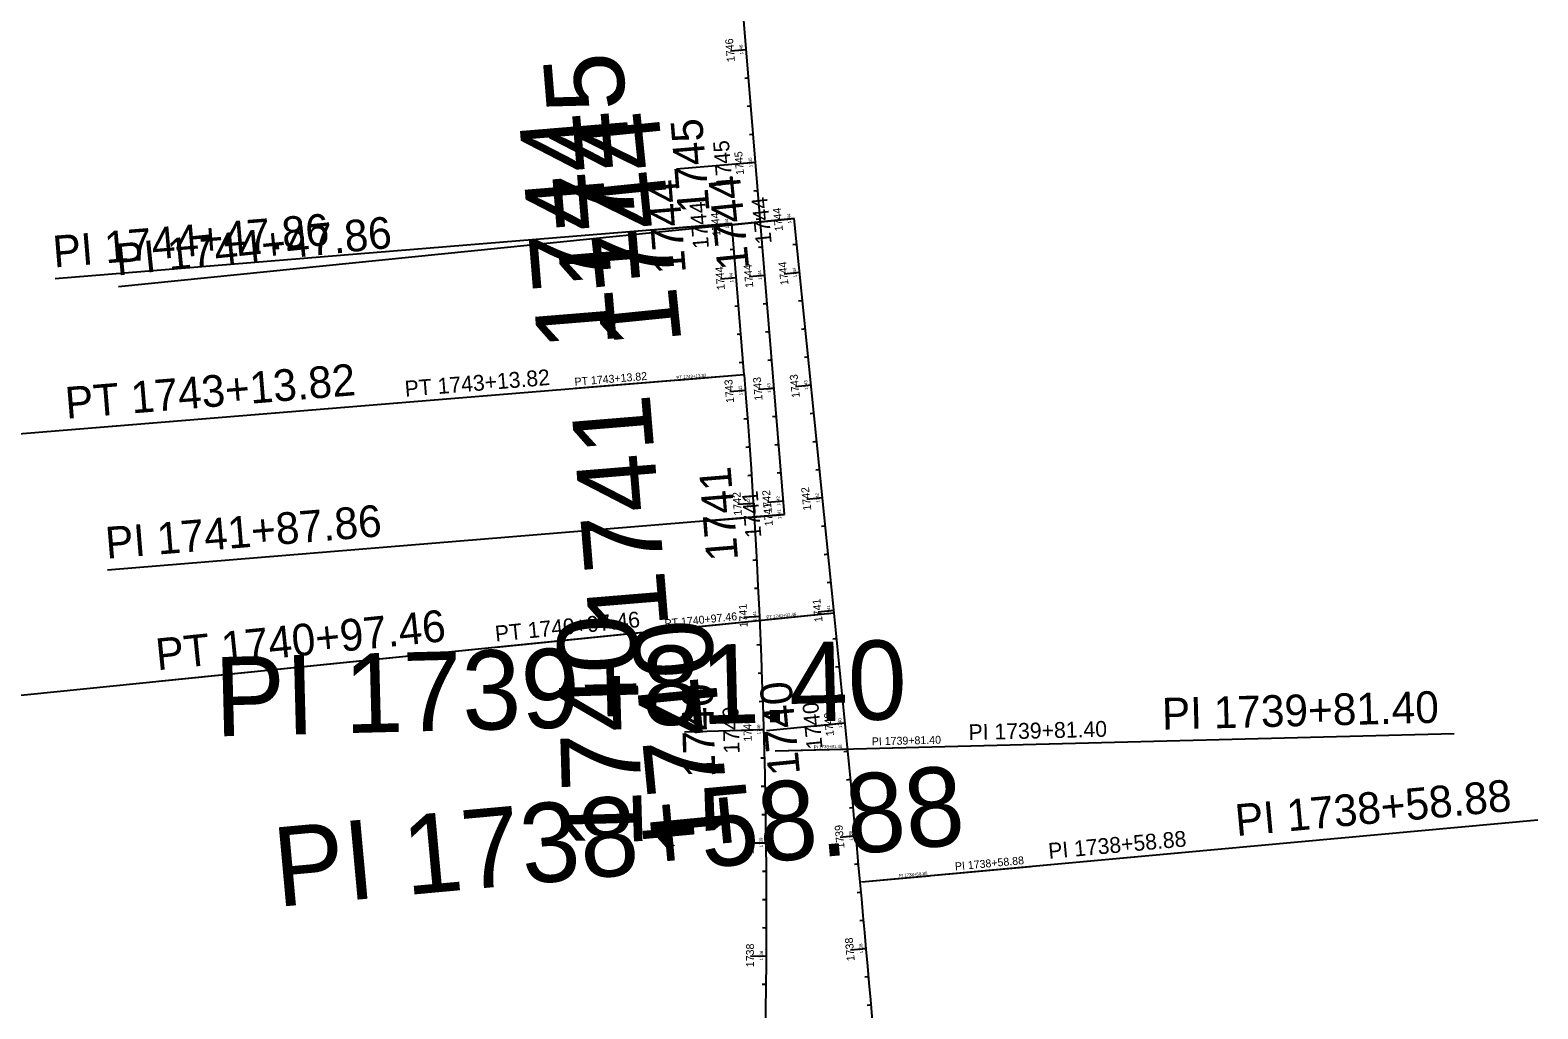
# Model space of a CAD drawing. Extents: x 353835 to 363333, y 126218 to 205387.
# Drawn here: x 360814 to 362146, y 132953 to 133817 of the extents above; entities that cross this region are included whole.
import ezdxf

# ---------------------------------------------------------------- set-up
doc = ezdxf.new("R2010")
doc.units = 0
for name, color, linetype in [('P_ALI_100_PIData', 7, 'Continuous'), ('P_ALI_100_Sta', 7, 'Continuous'), ('P_ALI_100_Tic', 7, 'Continuous'), ('P_ALI_20', 7, 'Continuous'), ('P_ALI_200_PIData', 7, 'Continuous'), ('P_ALI_200_Sta', 7, 'Continuous'), ('P_ALI_200_Tic', 7, 'Continuous'), ('P_ALI_20_PIData', 7, 'Continuous'), ('P_ALI_20_Sta', 7, 'Continuous'), ('P_ALI_20_Tic', 7, 'Continuous'), ('P_ALI_500_PIData', 7, 'Continuous'), ('P_ALI_500_Sta', 7, 'Continuous'), ('P_ALI_50_PIData', 7, 'Continuous'), ('P_ALI_50_Sta', 7, 'Continuous'), ('P_ALI_50_Tic', 7, 'Continuous')]:
    doc.layers.add(name, color=color, linetype=linetype)

msp = doc.modelspace()

# ---------------------------------------------------------------- linework, layer by layer
for points in [[(361494.2, 133603.3), (361494.2, 133603.3)], [(361504.3, 133503.8), (361504.3, 133503.8)], [(361514.3, 133404.3), (361514.4, 133404.3)], [(361524.4, 133304.9), (361524.4, 133304.9)], [(361543.8, 133105.8), (361543.8, 133105.8)], [(361552.9, 133006.2), (361552.9, 133006.2)]]:
    msp.add_lwpolyline(points)
at = {"layer": 'P_ALI_100_PIData'}
for points in [[(361445.2, 133512.8), (361146.2, 133488.4)], [(361445.2, 133512.8), (361385.4, 133507.9)], [(361524.7, 133302.3), (361226.2, 133272.1)], [(361524.7, 133302.3), (361465, 133296.3)], [(361472.4, 133180.8), (361772.3, 133188.4)], [(361472.4, 133180.8), (361532.4, 133182.3)], [(361548.7, 133064.9), (361847.5, 133092.3)], [(361548.7, 133064.9), (361608.5, 133070.4)]]:
    msp.add_lwpolyline(points, dxfattribs=at)
at = {"layer": 'P_ALI_100_Tic'}
for points in [[(361440, 133799.5), (361447, 133800.1)], [(361385.4, 133694.7), (361455.2, 133700.5)], [(361441.2, 133699.3), (361455.2, 133700.5)], [(361364.6, 133640.7), (361434.3, 133646.4)], [(361419.7, 133643.9), (361489.4, 133650.9)], [(361420.4, 133645.3), (361434.3, 133646.4)], [(361475.5, 133649.5), (361489.4, 133650.9)], [(361431.2, 133598.2), (361438.2, 133598.7)], [(361456.4, 133600.2), (361463.4, 133600.8)], [(361487.2, 133602.6), (361494.2, 133603.3)], [(361439.4, 133498.5), (361446.4, 133499.1)], [(361464.6, 133500.5), (361471.5, 133501.1)], [(361497.3, 133503.1), (361504.3, 133503.8)], [(361507.4, 133403.6), (361514.4, 133404.3)], [(361446.4, 133398.9), (361453.4, 133399.3)], [(361472.7, 133400.9), (361479.7, 133401.5)], [(361410.9, 133383.6), (361480.7, 133389.4)], [(361410.9, 133383.6), (361480.7, 133389.4)], [(361466.7, 133388.2), (361480.7, 133389.4)], [(361466.7, 133388.2), (361480.7, 133389.4)], [(361451.8, 133299.1), (361458.8, 133299.5)], [(361517.5, 133304.1), (361524.4, 133304.9)], [(361464.7, 133198.6), (361534.3, 133205.3)], [(361520.4, 133204), (361534.3, 133205.3)], [(361392.5, 133197.5), (361462.5, 133199.5)], [(361448.5, 133199.1), (361462.5, 133199.5)], [(361457.5, 133099.5), (361464.5, 133099.5)], [(361536.8, 133105.1), (361543.8, 133105.8)], [(361545.9, 133005.6), (361552.9, 133006.2)], [(361457.8, 132999.6), (361464.8, 132999.5)]]:
    msp.add_lwpolyline(points, dxfattribs=at)
at = {"layer": 'P_ALI_20'}
for p, q in [((361480.7, 133389.4), (361189, 136946.6)), ((361445.2, 133512.8), (361434.3, 133646.4)), ((361524.7, 133302.3), (361489.4, 133650.9))]:
    msp.add_line(p, q, dxfattribs=at)
for centre, radius, start, end in [((355564.9, 133031.9), 5900, 358.21215, 4.67542), ((336651.9, 130783.1), 25000, 4.68978, 5.78337)]:
    msp.add_arc(centre, radius, start, end, dxfattribs=at)
at = {"layer": 'P_ALI_200_PIData'}
for points in [[(361434.3, 133646.4), (360836.3, 133597.5)], [(361489.4, 133650.9), (360892.4, 133590.5)], [(361489.4, 133650.9), (360892.4, 133590.5)], [(361445.2, 133512.8), (360847.2, 133463.9)], [(361480.7, 133389.4), (360882.7, 133340.3)], [(361524.7, 133302.3), (360927.7, 133241.9)], [(361472.4, 133180.8), (362072.2, 133195.9)], [(361548.7, 133064.9), (362146.2, 133119.7)]]:
    msp.add_lwpolyline(points, dxfattribs=at)
at = {"layer": 'P_ALI_200_Tic'}
for points in [[(361433.1, 133799), (361447, 133800.1)], [(361427.3, 133698.2), (361455.2, 133700.5)], [(361406.4, 133644.1), (361434.3, 133646.4)], [(361461.5, 133648.1), (361489.4, 133650.9)], [(361461.5, 133648.1), (361489.4, 133650.9)], [(361424.3, 133597.6), (361438.2, 133598.7)], [(361449.4, 133599.6), (361463.4, 133600.8)], [(361480.3, 133601.9), (361494.2, 133603.3)], [(361432.4, 133498), (361446.4, 133499.1)], [(361457.6, 133500), (361471.5, 133501.1)], [(361490.4, 133502.4), (361504.3, 133503.8)], [(361500.4, 133402.9), (361514.4, 133404.3)], [(361439.5, 133398.4), (361453.4, 133399.3)], [(361465.8, 133400.3), (361479.7, 133401.5)], [(361452.8, 133387.1), (361480.7, 133389.4)], [(361452.8, 133387.1), (361480.7, 133389.4)], [(361444.8, 133298.8), (361458.8, 133299.5)], [(361510.5, 133303.4), (361524.4, 133304.9)], [(361506.5, 133202.6), (361534.3, 133205.3)], [(361434.5, 133198.7), (361462.5, 133199.5)], [(361450.5, 133099.4), (361464.5, 133099.5)], [(361529.9, 133104.5), (361543.8, 133105.8)], [(361539, 133005), (361552.9, 133006.2)], [(361450.8, 132999.6), (361464.8, 132999.5)]]:
    msp.add_lwpolyline(points, dxfattribs=at)
at = {"layer": 'P_ALI_20_Tic'}
for points in [[(361444.2, 133799.9), (361447, 133800.1)], [(361447.7, 133775.1), (361449.1, 133775.2)], [(361449.7, 133750.2), (361451.1, 133750.3)], [(361451.8, 133725.3), (361453.1, 133725.4)], [(361452.4, 133700.2), (361455.2, 133700.5)], [(361455.8, 133675.4), (361457.2, 133675.5)], [(361431.5, 133646.2), (361434.3, 133646.4)], [(361457.9, 133650.5), (361459.3, 133650.6)], [(361486.6, 133650.7), (361489.4, 133650.9)], [(361434.8, 133623.5), (361436.2, 133623.6)], [(361459.9, 133625.6), (361461.3, 133625.7)], [(361490.3, 133628.1), (361491.7, 133628.2)], [(361435.4, 133598.5), (361438.2, 133598.7)], [(361460.6, 133600.6), (361463.4, 133600.8)], [(361491.4, 133603), (361494.2, 133603.3)], [(361495.3, 133578.3), (361496.7, 133578.5)], [(361438.9, 133573.7), (361440.3, 133573.8)], [(361464, 133575.8), (361465.4, 133575.9)], [(361466.1, 133550.8), (361467.5, 133551)], [(361497.8, 133553.4), (361499.2, 133553.6)], [(361440.9, 133548.8), (361442.3, 133548.9)], [(361442.9, 133523.9), (361444.3, 133524)], [(361468.1, 133525.9), (361469.5, 133526)], [(361500.4, 133528.6), (361501.8, 133528.7)], [(361443.6, 133498.8), (361446.4, 133499.1)], [(361468.7, 133500.9), (361471.5, 133501.1)], [(361501.5, 133503.6), (361504.3, 133503.8)], [(361446.9, 133474), (361448.3, 133474.1)], [(361472.2, 133476.1), (361473.6, 133476.2)], [(361505.4, 133478.8), (361506.8, 133479)], [(361448.7, 133449.1), (361450.1, 133449.2)], [(361474.2, 133451.2), (361475.6, 133451.3)], [(361507.9, 133453.9), (361509.3, 133454.1)], [(361450.4, 133424.2), (361451.8, 133424.3)], [(361476.3, 133426.3), (361477.7, 133426.4)], [(361510.4, 133429.1), (361511.8, 133429.2)], [(361511.6, 133404.1), (361514.4, 133404.3)], [(361450.6, 133399.1), (361453.4, 133399.3)], [(361476.9, 133401.2), (361479.7, 133401.5)], [(361477.9, 133389.1), (361480.7, 133389.4)], [(361477.9, 133389.1), (361480.7, 133389.4)], [(361515.5, 133379.3), (361516.9, 133379.5)], [(361453.5, 133374.3), (361454.9, 133374.4)], [(361518, 133354.5), (361519.4, 133354.6)], [(361454.9, 133349.3), (361456.3, 133349.4)], [(361456.2, 133324.4), (361457.6, 133324.4)], [(361520.5, 133329.6), (361521.9, 133329.7)], [(361456, 133299.3), (361458.8, 133299.5)], [(361521.6, 133304.6), (361524.4, 133304.9)], [(361458.5, 133274.4), (361459.9, 133274.5)], [(361525.5, 133279.8), (361526.9, 133280)], [(361459.5, 133249.4), (361460.9, 133249.5)], [(361528, 133255), (361529.4, 133255.1)], [(361460.3, 133224.5), (361461.7, 133224.5)], [(361530.5, 133230.1), (361531.9, 133230.2)], [(361531.5, 133205.1), (361534.3, 133205.3)], [(361459.7, 133199.4), (361462.5, 133199.5)], [(361535.3, 133180.3), (361536.7, 133180.5)], [(361461.8, 133174.5), (361463.2, 133174.5)], [(361537.7, 133155.4), (361539.1, 133155.6)], [(361462.3, 133149.5), (361463.7, 133149.5)], [(361462.8, 133124.5), (361464.1, 133124.5)], [(361540.1, 133130.6), (361541.5, 133130.7)], [(361461.7, 133099.5), (361464.5, 133099.5)], [(361541, 133105.5), (361543.8, 133105.8)], [(361463.3, 133074.5), (361464.7, 133074.5)], [(361544.7, 133080.8), (361546.1, 133080.9)], [(361463.5, 133049.5), (361464.9, 133049.5)], [(361547, 133055.9), (361548.4, 133056)], [(361549.3, 133031), (361550.7, 133031.1)], [(361463.5, 133024.5), (361464.9, 133024.5)], [(361550.1, 133006), (361552.9, 133006.2)], [(361462, 132999.6), (361464.8, 132999.5)], [(361553.7, 132981.2), (361555.1, 132981.3)], [(361463.2, 132974.6), (361464.6, 132974.5)], [(361555.9, 132956.3), (361557.3, 132956.4)]]:
    msp.add_lwpolyline(points, dxfattribs=at)
at = {"layer": 'P_ALI_500_PIData'}
for points in [[(361445.2, 133512.8), (359950.2, 133390.6)], [(361524.7, 133302.3), (360032.3, 133151.2)], [(361472.4, 133180.8), (361622.4, 133184.6)], [(361548.7, 133064.9), (361698.1, 133078.6)]]:
    msp.add_lwpolyline(points, dxfattribs=at)
at = {"layer": 'P_ALI_50_PIData'}
for points in [[(361445.2, 133512.8), (361295.7, 133500.6)], [(361445.2, 133512.8), (361295.7, 133500.6)], [(361524.7, 133302.3), (361375.5, 133287.2)], [(361472.4, 133180.8), (361622.4, 133184.6)], [(361472.4, 133180.8), (361622.4, 133184.6)], [(361548.7, 133064.9), (361698.1, 133078.6)]]:
    msp.add_lwpolyline(points, dxfattribs=at)
at = {"layer": 'P_ALI_50_Tic'}
for points in [[(361440, 133799.5), (361447, 133800.1)], [(361445.6, 133774.9), (361449.1, 133775.2)], [(361447.6, 133750), (361451.1, 133750.3)], [(361449.7, 133725.1), (361453.1, 133725.4)], [(361448.2, 133699.9), (361455.2, 133700.5)], [(361453.7, 133675.2), (361457.2, 133675.5)], [(361427.3, 133645.9), (361434.3, 133646.4)], [(361427.3, 133645.9), (361434.3, 133646.4)], [(361455.8, 133650.3), (361459.3, 133650.6)], [(361482.4, 133650.2), (361489.4, 133650.9)], [(361432.7, 133623.4), (361436.2, 133623.6)], [(361432.7, 133623.4), (361436.2, 133623.6)], [(361457.8, 133625.4), (361461.3, 133625.7)], [(361488.2, 133627.8), (361491.7, 133628.2)], [(361431.2, 133598.2), (361438.2, 133598.7)], [(361431.2, 133598.2), (361438.2, 133598.7)], [(361456.4, 133600.2), (361463.4, 133600.8)], [(361487.2, 133602.6), (361494.2, 133603.3)], [(361493.2, 133578.1), (361496.7, 133578.5)], [(361436.8, 133573.5), (361440.3, 133573.8)], [(361436.8, 133573.5), (361440.3, 133573.8)], [(361461.9, 133575.6), (361465.4, 133575.9)], [(361464, 133550.7), (361467.5, 133551)], [(361495.8, 133553.2), (361499.2, 133553.6)], [(361438.8, 133548.6), (361442.3, 133548.9)], [(361438.8, 133548.6), (361442.3, 133548.9)], [(361440.8, 133523.7), (361444.3, 133524)], [(361440.8, 133523.7), (361444.3, 133524)], [(361466, 133525.8), (361469.5, 133526)], [(361498.3, 133528.4), (361501.8, 133528.7)], [(361439.4, 133498.5), (361446.4, 133499.1)], [(361439.4, 133498.5), (361446.4, 133499.1)], [(361464.6, 133500.5), (361471.5, 133501.1)], [(361497.3, 133503.1), (361504.3, 133503.8)], [(361444.8, 133473.9), (361448.3, 133474.1)], [(361444.8, 133473.9), (361448.3, 133474.1)], [(361470.1, 133475.9), (361473.6, 133476.2)], [(361503.3, 133478.6), (361506.8, 133479)], [(361446.6, 133449), (361450.1, 133449.2)], [(361446.6, 133449), (361450.1, 133449.2)], [(361472.1, 133451), (361475.6, 133451.3)], [(361505.8, 133453.7), (361509.3, 133454.1)], [(361448.3, 133424), (361451.8, 133424.3)], [(361448.3, 133424), (361451.8, 133424.3)], [(361474.2, 133426.1), (361477.7, 133426.4)], [(361508.4, 133428.9), (361511.8, 133429.2)], [(361507.4, 133403.6), (361514.4, 133404.3)], [(361446.4, 133398.9), (361453.4, 133399.3)], [(361446.4, 133398.9), (361453.4, 133399.3)], [(361472.7, 133400.9), (361479.7, 133401.5)], [(361473.7, 133388.8), (361480.7, 133389.4)], [(361473.7, 133388.8), (361480.7, 133389.4)], [(361513.4, 133379.1), (361516.9, 133379.5)], [(361451.4, 133374.2), (361454.9, 133374.4)], [(361451.4, 133374.2), (361454.9, 133374.4)], [(361515.9, 133354.2), (361519.4, 133354.6)], [(361452.8, 133349.2), (361456.3, 133349.4)], [(361452.8, 133349.2), (361456.3, 133349.4)], [(361454.1, 133324.3), (361457.6, 133324.4)], [(361454.1, 133324.3), (361457.6, 133324.4)], [(361518.4, 133329.4), (361521.9, 133329.7)], [(361451.8, 133299.1), (361458.8, 133299.5)], [(361451.8, 133299.1), (361458.8, 133299.5)], [(361517.5, 133304.1), (361524.4, 133304.9)], [(361456.4, 133274.3), (361459.9, 133274.5)], [(361456.4, 133274.3), (361459.9, 133274.5)], [(361523.5, 133279.6), (361526.9, 133280)], [(361457.4, 133249.4), (361460.9, 133249.5)], [(361457.4, 133249.4), (361460.9, 133249.5)], [(361525.9, 133254.8), (361529.4, 133255.1)], [(361458.2, 133224.4), (361461.7, 133224.5)], [(361458.2, 133224.4), (361461.7, 133224.5)], [(361528.4, 133229.9), (361531.9, 133230.2)], [(361527.4, 133204.7), (361534.3, 133205.3)], [(361455.5, 133199.3), (361462.5, 133199.5)], [(361455.5, 133199.3), (361462.5, 133199.5)], [(361533.2, 133180.1), (361536.7, 133180.5)], [(361459.7, 133174.4), (361463.2, 133174.5)], [(361459.7, 133174.4), (361463.2, 133174.5)], [(361535.6, 133155.2), (361539.1, 133155.6)], [(361460.2, 133149.5), (361463.7, 133149.5)], [(361460.2, 133149.5), (361463.7, 133149.5)], [(361460.7, 133124.5), (361464.1, 133124.5)], [(361460.7, 133124.5), (361464.1, 133124.5)], [(361538, 133130.4), (361541.5, 133130.7)], [(361457.5, 133099.5), (361464.5, 133099.5)], [(361457.5, 133099.5), (361464.5, 133099.5)], [(361536.8, 133105.1), (361543.8, 133105.8)], [(361461.2, 133074.5), (361464.7, 133074.5)], [(361461.2, 133074.5), (361464.7, 133074.5)], [(361542.6, 133080.6), (361546.1, 133080.9)], [(361461.4, 133049.5), (361464.9, 133049.5)], [(361461.4, 133049.5), (361464.9, 133049.5)], [(361544.9, 133055.7), (361548.4, 133056)], [(361547.2, 133030.8), (361550.7, 133031.1)], [(361461.4, 133024.6), (361464.9, 133024.5)], [(361461.4, 133024.6), (361464.9, 133024.5)], [(361545.9, 133005.6), (361552.9, 133006.2)], [(361457.8, 132999.6), (361464.8, 132999.5)], [(361457.8, 132999.6), (361464.8, 132999.5)], [(361551.6, 132981), (361555.1, 132981.3)], [(361461.1, 132974.6), (361464.6, 132974.5)], [(361461.1, 132974.6), (361464.6, 132974.5)], [(361553.8, 132956.1), (361557.3, 132956.4)]]:
    msp.add_lwpolyline(points, dxfattribs=at)

# ---------------------------------------------------------------- texts
at = {"layer": 'P_ALI_100_PIData'}
for s, rotation, p in [('PT 1743+13.82', 4.6754, (361145.8, 133493.4)), ('PT 1740+97.46', 5.7834, (361225.7, 133277.1)), ('PI 1739+81.40', 1.4438, (361643.5, 133190.1)), ('PI 1738+58.88', 5.2366, (361714.4, 133085.2))]:
    msp.add_text(s, height=14, rotation=rotation, dxfattribs=at).set_placement(p)
at = {"layer": 'P_ALI_100_Sta'}
for s, rotation, p in [('1745', 94.6882, (361434.9, 133678.8)), ('1744', 94.6754, (361414, 133624.7)), ('1744', 95.7834, (361469.5, 133628.9)), ('1744', 95.7834, (361469.5, 133628.9)), ('1741', 94.6882, (361460.3, 133369.4)), ('1741', 94.6882, (361460.3, 133369.4)), ('1740', 91.6279, (361441.1, 133178.4)), ('1740', 95.56, (361514.4, 133182.8))]:
    msp.add_text(s, height=14, rotation=rotation, dxfattribs=at).set_placement(p)
at = {"layer": 'P_ALI_200_PIData'}
for s, rotation, p in [('PI 1744+47.86', 4.6754, (360835.5, 133607.5)), ('PI 1744+47.86', 5.7834, (360891.4, 133600.4)), ('PI 1744+47.86', 5.7834, (360891.4, 133600.4)), ('PT 1743+13.82', 4.6754, (360846.4, 133473.9)), ('PI 1741+87.86', 4.6882, (360881.9, 133350.3)), ('PT 1740+97.46', 5.7834, (360926.7, 133251.8)), ('PI 1739+81.40', 1.4438, (361814.5, 133199.4)), ('PI 1738+58.88', 5.2366, (361880.1, 133105.4))]:
    msp.add_text(s, height=28, rotation=rotation, dxfattribs=at).set_placement(p)
at = {"layer": 'P_ALI_200_Sta'}
for s, rotation, p in [('1745', 94.6882, (361414.6, 133657.1)), ('1744', 94.6754, (361393.7, 133603.1)), ('1744', 95.7834, (361449.6, 133606.8)), ('1744', 95.7834, (361449.6, 133606.8)), ('1741', 94.6882, (361439.8, 133349.5)), ('1741', 94.6882, (361439.8, 133349.5)), ('1740', 91.6279, (361419.7, 133157.3)), ('1740', 95.56, (361494.5, 133160.3))]:
    msp.add_text(s, height=28, rotation=rotation, dxfattribs=at).set_placement(p)
at = {"layer": 'P_ALI_20_PIData'}
for s, rotation, p in [('PT 1743+13.82', 4.6754, (361385.4, 133508.9)), ('PT 1740+97.46', 5.7834, (361464.9, 133297.3)), ('PT 1740+97.46', 5.7834, (361464.9, 133297.3)), ('PI 1739+81.40', 1.4438, (361506.6, 133182.7)), ('PI 1738+58.88', 5.2366, (361581.9, 133069))]:
    msp.add_text(s, height=2.8, rotation=rotation, dxfattribs=at).set_placement(p)
at = {"layer": 'P_ALI_20_Sta'}
for s, rotation, p in [('1746', 94.6882, (361444.3, 133795.9)), ('1745', 94.6882, (361452.4, 133696.2)), ('1744', 94.6754, (361431.6, 133642.2)), ('1744', 95.7834, (361486.7, 133646.7)), ('1744', 94.6882, (361460.6, 133596.6)), ('1744', 95.7834, (361491.5, 133599)), ('1744', 94.6754, (361435.5, 133594.5)), ('1743', 94.5412, (361443.6, 133494.8)), ('1743', 94.6882, (361468.8, 133496.9)), ('1743', 95.7834, (361501.6, 133499.6)), ('1742', 94.6882, (361477, 133397.2)), ('1742', 95.7834, (361511.7, 133400.1)), ('1742', 93.5701, (361450.6, 133395.1)), ('1741', 94.6882, (361477.9, 133385.5)), ('1741', 94.6882, (361477.9, 133385.5)), ('1741', 92.599, (361455.9, 133295.7)), ('1741', 95.7834, (361521.7, 133300.9)), ('1740', 95.56, (361531.7, 133201)), ('1740', 91.6279, (361459.5, 133195.3)), ('1739', 90.6568, (361461.5, 133095.5)), ('1739', 95.3308, (361541.1, 133101.5)), ('1738', 95.1016, (361550.2, 133002)), ('1738', 89.6856, (361461.7, 132995.6))]:
    msp.add_text(s, height=2.8, rotation=rotation, dxfattribs=at).set_placement(p)
at = {"layer": 'P_ALI_500_PIData'}
for s, rotation, p in [('PI 1739+81.40', 1.4438, (360978.1, 133193.4)), ('PI 1738+58.88', 5.2366, (361032.8, 133042.8))]:
    msp.add_text(s, height=70, rotation=rotation, dxfattribs=at).set_placement(p)
at = {"layer": 'P_ALI_500_Sta'}
for s, rotation, p in [('1745', 94.6882, (361353.7, 133592)), ('1744', 94.6754, (361332.8, 133538)), ('1744', 95.7834, (361390, 133540.6)), ('1741', 94.6882, (361378.5, 133289.7)), ('1741', 94.6882, (361378.5, 133289.7)), ('1740', 91.6279, (361355.5, 133093.9)), ('1740', 95.56, (361434.8, 133092.6))]:
    msp.add_text(s, height=70, rotation=rotation, dxfattribs=at).set_placement(p)
at = {"layer": 'P_ALI_50_PIData'}
for s, rotation, p in [('PT 1743+13.82', 4.6754, (361295.5, 133503.1)), ('PT 1743+13.82', 4.6754, (361295.5, 133503.1)), ('PT 1740+97.46', 5.7834, (361375.2, 133289.7)), ('PI 1739+81.40', 1.4438, (361557.9, 133185.5)), ('PI 1739+81.40', 1.4438, (361557.9, 133185.5)), ('PI 1738+58.88', 5.2366, (361631.6, 133075.1))]:
    msp.add_text(s, height=7, rotation=rotation, dxfattribs=at).set_placement(p)
at = {"layer": 'P_ALI_50_Sta'}
for s, rotation, p in [('1746', 94.6882, (361436.9, 133789.3)), ('1745', 94.6882, (361445, 133689.6)), ('1744', 95.7834, (361479.4, 133639.9)), ('1744', 95.7834, (361479.4, 133639.9)), ('1744', 95.7834, (361479.4, 133639.9)), ('1744', 94.6754, (361424.2, 133635.6)), ('1744', 94.6754, (361424.2, 133635.6)), ('1744', 94.6754, (361428.1, 133587.9)), ('1744', 94.6754, (361428.1, 133587.9)), ('1744', 94.6882, (361453.2, 133589.9)), ('1744', 95.7834, (361484.3, 133592.3)), ('1743', 95.7834, (361494.3, 133492.8)), ('1743', 94.5412, (361436.2, 133488.2)), ('1743', 94.5412, (361436.2, 133488.2)), ('1743', 94.6882, (361461.4, 133490.3)), ('1742', 93.5701, (361443.1, 133388.7)), ('1742', 93.5701, (361443.1, 133388.7)), ('1742', 94.6882, (361469.6, 133390.6)), ('1742', 95.7834, (361504.4, 133393.3)), ('1741', 94.6882, (361470.5, 133379.4)), ('1741', 94.6882, (361470.5, 133379.4)), ('1741', 95.7834, (361514.4, 133294.7)), ('1741', 92.599, (361448.2, 133289.9)), ('1741', 92.599, (361448.2, 133289.9)), ('1740', 91.6279, (361451.8, 133189)), ('1740', 91.6279, (361451.8, 133189)), ('1740', 95.56, (361524.4, 133194.1)), ('1739', 95.3308, (361533.8, 133094.8)), ('1739', 90.6568, (361453.6, 133089.4)), ('1739', 90.6568, (361453.6, 133089.4)), ('1738', 89.6856, (361453.7, 132989.6)), ('1738', 89.6856, (361453.7, 132989.6)), ('1738', 95.1016, (361542.8, 132995.3))]:
    msp.add_text(s, height=7, rotation=rotation, dxfattribs=at).set_placement(p)

doc.saveas('drawing.dxf')
